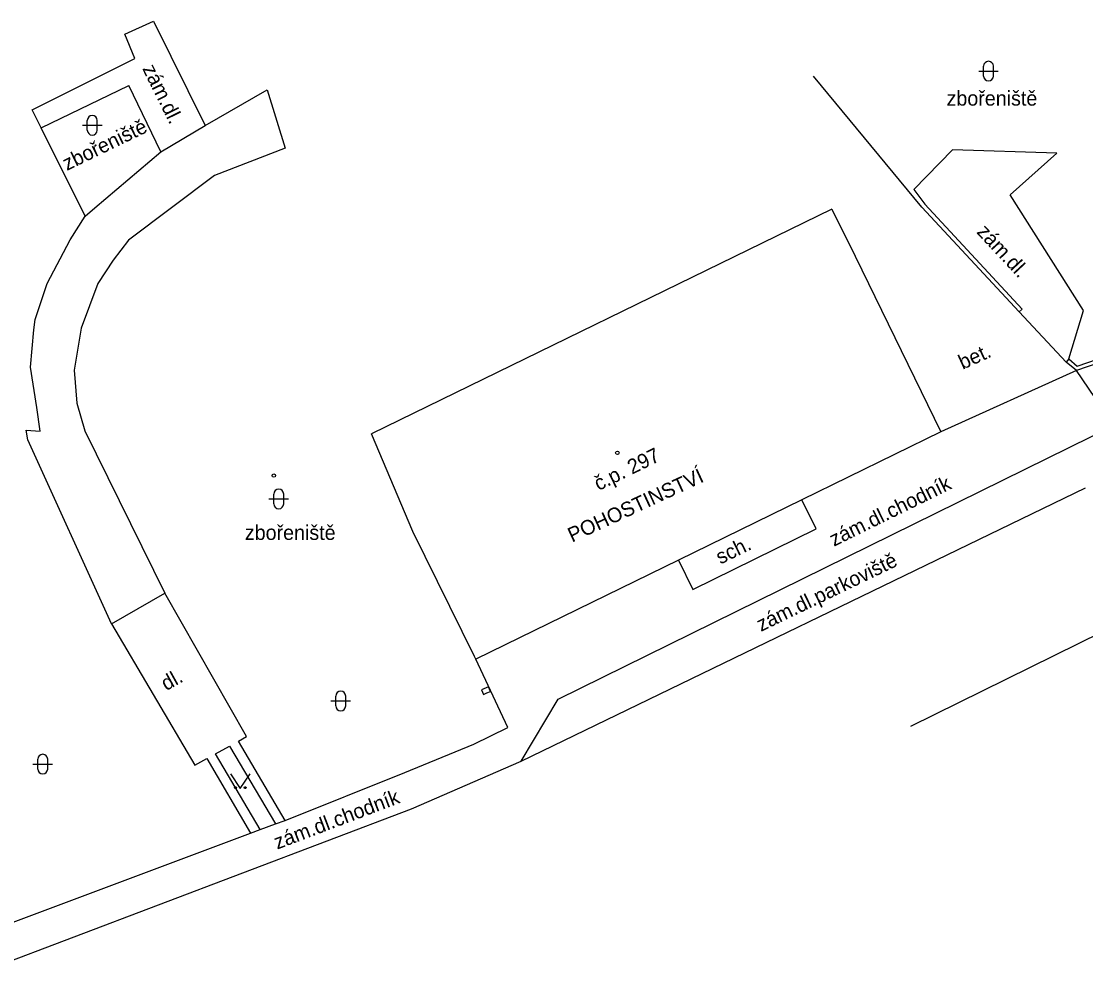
# Model space of a CAD drawing. Extents: x -577457 to -568404, y -1208466 to -1201387.
# Drawn here: x -569433.4 to -569379.2, y -1204773.2 to -1204724.9 of the extents above; entities that cross this region are included whole.
import ezdxf

# ---------------------------------------------------------------- set-up
doc = ezdxf.new("R2010")
doc.units = 0
for name, color, linetype in [('BUDOVY_MĚŘ', 7, 'Continuous'), ('BUDOVY_NEMĚŘ', 7, 'Continuous'), ('OBVOD_PILÍŘE', 7, 'Continuous'), ('POMOC_POPIS', 7, 'Continuous'), ('ROZHRANÍ_PLOCH', 7, 'Continuous'), ('ZN_BUDOV', 7, 'Continuous'), ('ZN_DOPLŇKOVÉ', 7, 'Continuous'), ('ZN_KULTUR', 7, 'Continuous'), ('Č_POPIS_ORIENT', 7, 'Continuous')]:
    doc.layers.add(name, color=color, linetype=linetype)

msp = doc.modelspace()

# ---------------------------------------------------------------- linework, layer by layer
at = {"layer": 'BUDOVY_MĚŘ'}
for points in [[(-569392.1, -1204734.43), (-569390.9, -1204736.82)], [(-569390.9, -1204736.82), (-569386.54, -1204745.78)], [(-569386.54, -1204745.78), (-569393.62, -1204749.24)], [(-569393.62, -1204749.24), (-569399.91, -1204752.32)], [(-569410.31, -1204757.24), (-569413.46, -1204750.86)], [(-569399.91, -1204752.32), (-569410.24, -1204757.37)], [(-569410.24, -1204757.37), (-569410.31, -1204757.24)]]:
    msp.add_lwpolyline(points, dxfattribs=at)
at = {"layer": 'BUDOVY_NEMĚŘ'}
for points in [[(-569392.1, -1204734.43), (-569415.56, -1204745.88)], [(-569413.46, -1204750.86), (-569415.56, -1204745.88)]]:
    msp.add_lwpolyline(points, dxfattribs=at)
at = {"layer": 'OBVOD_PILÍŘE'}
msp.add_lwpolyline([(-569409.68, -1204759.09), (-569409.5, -1204759.01), (-569409.6, -1204758.78), (-569409.96, -1204758.94), (-569409.86, -1204759.17), (-569409.68, -1204759.09)], dxfattribs=at)
at = {"layer": 'ROZHRANÍ_PLOCH'}
for points in [[(-569432.41, -1204730.28), (-569432.86, -1204729.37), (-569427.62, -1204726.75), (-569428.14, -1204725.5), (-569426.68, -1204724.85), (-569424.05, -1204730.16)], [(-569432.41, -1204730.28), (-569427.94, -1204728.12)], [(-569424.05, -1204730.16), (-569420.89, -1204728.35), (-569419.97, -1204731.32), (-569423.56, -1204732.71), (-569427.95, -1204736.01), (-569428.73, -1204737.02), (-569429.52, -1204738.22), (-569430.37, -1204740.49), (-569430.72, -1204742.64), (-569430.59, -1204744.31), (-569430.17, -1204745.73), (-569426.09, -1204754.01)], [(-569426.3, -1204731.5), (-569427.94, -1204728.12)], [(-569430.16, -1204734.78), (-569432.41, -1204730.28)], [(-569426.3, -1204731.5), (-569424.05, -1204730.16)], [(-569430.16, -1204734.78), (-569429.66, -1204734.36), (-569426.3, -1204731.5)], [(-569387.92, -1204733.43), (-569385.95, -1204731.41)], [(-569380.02, -1204742.06), (-569379.27, -1204739.59), (-569383, -1204733.69), (-569380.62, -1204731.58), (-569385.95, -1204731.41)], [(-569428.82, -1204755.57), (-569433.08, -1204746.18), (-569433.16, -1204745.69), (-569432.46, -1204745.74), (-569432.62, -1204744.54), (-569432.94, -1204742.49), (-569432.77, -1204740.58), (-569432.7, -1204740.06), (-569432.1, -1204738.21), (-569430.92, -1204735.99), (-569430.16, -1204734.78)], [(-569388.07, -1204760.79), (-569338.02, -1204736.11)], [(-569379.63, -1204742.66), (-569386.54, -1204745.78)], [(-569377.72, -1204745.46), (-569379.63, -1204742.66)], [(-569407.94, -1204762.57), (-569406.04, -1204759.41), (-569377.72, -1204745.46)], [(-569407.94, -1204762.57), (-569379.16, -1204748.64)], [(-569428.82, -1204755.57), (-569426.09, -1204754.01)], [(-569422.35, -1204761.55), (-569421.94, -1204761.32), (-569426.09, -1204754.01)], [(-569428.82, -1204755.57), (-569424.57, -1204762.78), (-569423.95, -1204762.44)], [(-569419.97, -1204765.59), (-569413.87, -1204763.15), (-569410.34, -1204761.7), (-569408.61, -1204760.85), (-569410.24, -1204757.37)], [(-569421.24, -1204766.06), (-569423.52, -1204762.2), (-569422.8, -1204761.8), (-569420.45, -1204765.77)], [(-569419.97, -1204765.59), (-569422.35, -1204761.55)], [(-569423.95, -1204762.44), (-569421.73, -1204766.24)], [(-569435.03, -1204773.15), (-569413.52, -1204765), (-569407.94, -1204762.57)], [(-569421.24, -1204766.06), (-569420.45, -1204765.77)], [(-569420.45, -1204765.77), (-569419.97, -1204765.59)], [(-569438.19, -1204772.41), (-569421.73, -1204766.24)], [(-569421.73, -1204766.24), (-569421.24, -1204766.06)]]:
    msp.add_lwpolyline(points, dxfattribs=at)
at = {"layer": 'ZN_BUDOV'}
for centre in [(-569403.03, -1204746.85), (-569420.54, -1204748.01)]:
    msp.add_circle(centre, 0.0875, dxfattribs=at)
at = {"layer": 'ZN_DOPLŇKOVÉ'}
for points in [[(-569387.51, -1204734.32), (-569393.03, -1204727.64)], [(-569387.92, -1204733.43), (-569387.36, -1204734.18), (-569382.39, -1204739.52), (-569382.54, -1204739.66)], [(-569382.54, -1204739.66), (-569387.51, -1204734.32)], [(-569380.02, -1204742.06), (-569379.59, -1204742.44), (-569370.16, -1204739.18)], [(-569382.54, -1204739.66), (-569380.15, -1204742.22)], [(-569370.03, -1204739.35), (-569379.63, -1204742.66)], [(-569380.02, -1204742.06), (-569380.15, -1204742.22)], [(-569379.63, -1204742.66), (-569380.15, -1204742.22)], [(-569399.91, -1204752.32), (-569399.18, -1204753.81), (-569392.89, -1204750.73), (-569393.62, -1204749.24)]]:
    msp.add_lwpolyline(points, dxfattribs=at)
at = {"layer": 'ZN_KULTUR'}
for p, q in [((-569384.36, -1204727.64), (-569384.36, -1204727.14)), ((-569383.86, -1204727.64), (-569383.86, -1204727.14)), ((-569384.61, -1204727.39), (-569383.61, -1204727.39)), ((-569430.05, -1204730.4), (-569430.05, -1204729.9)), ((-569429.55, -1204730.4), (-569429.55, -1204729.9)), ((-569430.3, -1204730.15), (-569429.3, -1204730.15)), ((-569420.54, -1204749.45), (-569420.54, -1204748.95)), ((-569420.04, -1204749.45), (-569420.04, -1204748.95)), ((-569420.79, -1204749.2), (-569419.79, -1204749.2)), ((-569417.38, -1204759.75), (-569417.38, -1204759.25)), ((-569416.88, -1204759.75), (-569416.88, -1204759.25)), ((-569417.63, -1204759.5), (-569416.63, -1204759.5)), ((-569432.57, -1204762.97), (-569432.57, -1204762.47)), ((-569432.07, -1204762.97), (-569432.07, -1204762.47)), ((-569432.82, -1204762.72), (-569431.82, -1204762.72))]:
    msp.add_line(p, q, dxfattribs=at)
msp.add_lwpolyline([(-569422.75, -1204763.22), (-569422.25, -1204763.97), (-569421.75, -1204763.22)], dxfattribs=at)
for centre in [(-569422.5, -1204763.92), (-569422, -1204763.92)]:
    msp.add_circle(centre, 0.05, dxfattribs=at)
for centre, start, end in [((-569384.11, -1204727.14), 0, 180), ((-569384.11, -1204727.64), 180, 360), ((-569429.8, -1204729.9), 0, 180), ((-569429.8, -1204730.4), 180, 360), ((-569420.29, -1204748.95), 0, 180), ((-569420.29, -1204749.45), 180, 360), ((-569417.13, -1204759.25), 0, 180), ((-569417.13, -1204759.75), 180, 360), ((-569432.32, -1204762.47), 0, 180), ((-569432.32, -1204762.97), 180, 360)]:
    msp.add_arc(centre, 0.25, start, end, dxfattribs=at)

# ---------------------------------------------------------------- texts
at = {"layer": 'POMOC_POPIS'}
for s, rotation, p in [('zám.dl.', 296.3488, (-569427.26, -1204727.26)), ('zbořeniště', 25.7908, (-569431.09, -1204732.48)), ('zám.dl.', 312.9447, (-569384.75, -1204735.62)), ('bet.', 24.3001, (-569385.43, -1204742.62)), ('POHOSTINSTVÍ', 24.77, (-569405.34, -1204751.43)), ('zám.dl.chodník', 26.2242, (-569391.99, -1204751.64)), ('sch.', 26.0894, (-569397.78, -1204752.55)), ('zám.dl.parkoviště', 25.8277, (-569395.71, -1204755.98)), ('dl.', 29.04, (-569426.03, -1204759)), ('zám.dl.chodník', 20.7715, (-569420.37, -1204767.08))]:
    msp.add_text(s, height=0.75, rotation=rotation, dxfattribs=at).set_placement(p)
for p in [(-569386.25, -1204729.15), (-569422.02, -1204751.29)]:
    msp.add_text('zbořeniště', height=0.75, dxfattribs=at).set_placement(p)
at = {"layer": 'Č_POPIS_ORIENT'}
msp.add_text('č.p. 297', height=0.75, rotation=26.09, dxfattribs=at).set_placement((-569403.99, -1204748.8))

doc.saveas('drawing.dxf')
